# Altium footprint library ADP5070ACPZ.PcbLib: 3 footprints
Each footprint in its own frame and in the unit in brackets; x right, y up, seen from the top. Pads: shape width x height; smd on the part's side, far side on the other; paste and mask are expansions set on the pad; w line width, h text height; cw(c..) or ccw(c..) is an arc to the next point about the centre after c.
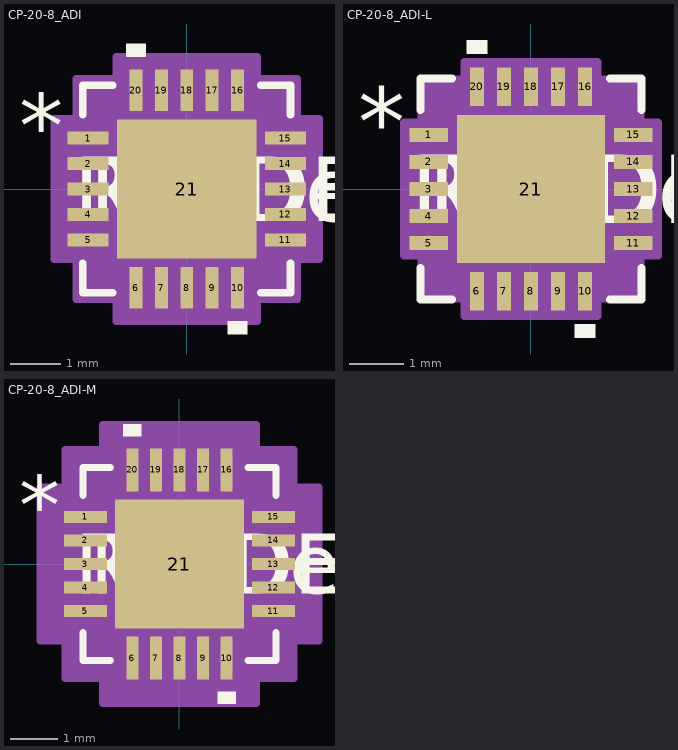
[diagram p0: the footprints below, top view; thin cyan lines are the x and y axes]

## CP-20-8_ADI [mil]
pads (21):
  rect 32x10 smd paste+0 mask+0: 1(-76.5,39.37) 2(-76.5,19.68) 3(-76.5,0) 4(-76.5,-19.68) 5(-76.5,-39.37) 11(76.5,-39.37) 12(76.5,-19.68) 13(76.5,0) 14(76.5,19.68) 15(76.5,39.37)
  rect 10x32 smd paste+0 mask+0: 6(-39.37,-76.5) 7(-19.68,-76.5) 8(0,-76.5) 9(19.68,-76.5) 10(39.37,-76.5) 16(39.37,76.5) 17(19.68,76.5) 18(0,76.5) 19(-19.68,76.5) 20(-39.37,76.5)
  rect 108x108 smd paste-54 mask+0: 21(0,0)
Top Overlay:
  region: 46.87,-102.5 31.87,-102.5 31.87,-112.5 46.87,-112.5
  region: -31.87,102.5 -46.87,102.5 -46.87,112.5 -31.87,112.5
  lines w6: -80.5,-57.47 -80.5,-80.5 -57.47,-80.5 ; -80.5,57.47 -80.5,80.5 -57.47,80.5 ; 57.47,-80.5 80.5,-80.5 80.5,-57.47 ; 57.47,80.5 80.5,80.5 80.5,57.47
  text "*" at -130,24.21 h50
  text "RefDes" at -75,-25 h50
  text "REFDES" at -87.5,-25 h50
Top Paste:
  region: -3.94,50.06 -50.06,50.06 -50.06,3.94 -3.94,3.94
  region: -3.94,-3.94 -50.06,-3.94 -50.06,-50.06 -3.94,-50.06
  region: 50.06,50.06 3.94,50.06 3.94,3.94 50.06,3.94
  region: 50.06,-3.94 3.94,-3.94 3.94,-50.06 50.06,-50.06
Mechanical 13:
  lines w1: -75.5,25.5 -25.5,75.5 ; -75.5,-75.5 75.5,-75.5 ; -75.5,-75.5 -75.5,75.5 ; -75.5,-75.5 -75.5,-75.5 ; -75.5,75.5 75.5,75.5 ; -75.5,75.5 -75.5,75.5 ; 75.5,-75.5 75.5,-75.5 ; 75.5,-75.5 75.5,75.5 ; 75.5,75.5 75.5,75.5 ; -80.5,-45.37 -80.5,-33.37 -75.5,-33.37 -75.5,-45.37 -80.5,-45.37 ; -80.5,-25.68 -80.5,-13.69 -75.5,-13.69 -75.5,-25.68 -80.5,-25.68 ; -80.5,-6 -80.5,6 -75.5,6 -75.5,-6 -80.5,-6 ; -80.5,13.69 -80.5,25.68 -75.5,25.68 -75.5,13.69 -80.5,13.69 ; -80.5,33.37 -80.5,45.37 -75.5,45.37 -75.5,33.37 -80.5,33.37 ; -45.37,-80.5 -45.37,-75.5 -33.37,-75.5 -33.37,-80.5 -45.37,-80.5 ; -45.37,75.5 -33.37,75.5 -33.37,80.5 -45.37,80.5 -45.37,75.5 ; -25.68,-80.5 -25.68,-75.5 -13.69,-75.5 -13.69,-80.5 -25.68,-80.5 ; -25.68,75.5 -13.69,75.5 -13.69,80.5 -25.68,80.5 -25.68,75.5 ; -6,-80.5 -6,-75.5 6,-75.5 6,-80.5 -6,-80.5 ; -6,75.5 6,75.5 6,80.5 -6,80.5 -6,75.5 ; 13.69,-80.5 13.69,-75.5 25.68,-75.5 25.68,-80.5 13.69,-80.5 ; 13.69,75.5 25.68,75.5 25.68,80.5 13.69,80.5 13.69,75.5 ; 33.37,-80.5 33.37,-75.5 45.37,-75.5 45.37,-80.5 33.37,-80.5 ; 33.37,75.5 45.37,75.5 45.37,80.5 33.37,80.5 33.37,75.5 ; 75.5,-45.37 75.5,-33.37 80.5,-33.37 80.5,-45.37 75.5,-45.37 ; 75.5,-25.68 75.5,-13.69 80.5,-13.69 80.5,-25.68 75.5,-25.68 ; 75.5,-6 75.5,6 80.5,6 80.5,-6 75.5,-6 ; 75.5,13.69 75.5,25.68 80.5,25.68 80.5,13.69 75.5,13.69 ; 75.5,33.37 75.5,45.37 80.5,45.37 80.5,33.37 75.5,33.37
  text "*" at -73,24.21 h50
  text "RefDes2" at -87.5,-25 h50
Mechanical 15:
  region: -54.37,-85.5 -85.5,-85.5 -85.5,-54.37 -102.5,-54.37 -102.5,54.37 -85.5,54.37 -85.5,85.5 -54.37,85.5 -54.37,102.5 54.37,102.5 54.37,85.5 85.5,85.5 85.5,54.37 102.5,54.37 102.5,-54.37 85.5,-54.37 85.5,-85.5 54.37,-85.5 54.37,-102.5 -54.37,-102.5
  lines w6: -102.5,-54.37 -85.5,-54.37 -85.5,-85.5 -54.37,-85.5 -54.37,-102.5 54.37,-102.5 54.37,-85.5 85.5,-85.5 85.5,-54.37 102.5,-54.37 102.5,54.37 85.5,54.37 85.5,85.5 54.37,85.5 54.37,102.5 -54.37,102.5 -54.37,85.5 -85.5,85.5 -85.5,54.37 -102.5,54.37 -102.5,-54.37
3D body "CP-20-8_ADI.step": height 32.09, standoff 0, extent -80.51,-80.51 80.51,80.51

## CP-20-8_ADI-L [mil]
pads (21):
  rect 28x10 smd paste+0 mask+0: 1(-74.5,39.37) 2(-74.5,19.68) 3(-74.5,0) 4(-74.5,-19.68) 5(-74.5,-39.37) 11(74.5,-39.37) 12(74.5,-19.68) 13(74.5,0) 14(74.5,19.68) 15(74.5,39.37)
  rect 10x28 smd paste+0 mask+0: 6(-39.37,-74.5) 7(-19.68,-74.5) 8(0,-74.5) 9(19.68,-74.5) 10(39.37,-74.5) 16(39.37,74.5) 17(19.68,74.5) 18(0,74.5) 19(-19.68,74.5) 20(-39.37,74.5)
  rect 108x108 smd paste-54 mask+0: 21(0,0)
Top Overlay:
  region: 46.87,-98.5 31.87,-98.5 31.87,-108.5 46.87,-108.5
  region: -31.87,98.5 -46.87,98.5 -46.87,108.5 -31.87,108.5
  lines w6: -80.5,-57.47 -80.5,-80.5 -57.47,-80.5 ; -80.5,57.47 -80.5,80.5 -57.47,80.5 ; 57.47,-80.5 80.5,-80.5 80.5,-57.47 ; 57.47,80.5 80.5,80.5 80.5,57.47
  text "*" at -126,24.21 h50
  text "RefDes" at -75,-25 h50
  text "REFDES" at -87.5,-25 h50
Top Paste:
  region: -3.94,50.06 -50.06,50.06 -50.06,3.94 -3.94,3.94
  region: -3.94,-3.94 -50.06,-3.94 -50.06,-50.06 -3.94,-50.06
  region: 50.06,50.06 3.94,50.06 3.94,3.94 50.06,3.94
  region: 50.06,-3.94 3.94,-3.94 3.94,-50.06 50.06,-50.06
Mechanical 13:
  lines w1: -75.5,25.5 -25.5,75.5 ; -75.5,-75.5 75.5,-75.5 ; -75.5,-75.5 -75.5,75.5 ; -75.5,-75.5 -75.5,-75.5 ; -75.5,75.5 75.5,75.5 ; -75.5,75.5 -75.5,75.5 ; 75.5,-75.5 75.5,-75.5 ; 75.5,-75.5 75.5,75.5 ; 75.5,75.5 75.5,75.5 ; -80.5,-45.37 -80.5,-33.37 -75.5,-33.37 -75.5,-45.37 -80.5,-45.37 ; -80.5,-25.68 -80.5,-13.69 -75.5,-13.69 -75.5,-25.68 -80.5,-25.68 ; -80.5,-6 -80.5,6 -75.5,6 -75.5,-6 -80.5,-6 ; -80.5,13.69 -80.5,25.68 -75.5,25.68 -75.5,13.69 -80.5,13.69 ; -80.5,33.37 -80.5,45.37 -75.5,45.37 -75.5,33.37 -80.5,33.37 ; -45.37,-80.5 -45.37,-75.5 -33.37,-75.5 -33.37,-80.5 -45.37,-80.5 ; -45.37,75.5 -33.37,75.5 -33.37,80.5 -45.37,80.5 -45.37,75.5 ; -25.68,-80.5 -25.68,-75.5 -13.69,-75.5 -13.69,-80.5 -25.68,-80.5 ; -25.68,75.5 -13.69,75.5 -13.69,80.5 -25.68,80.5 -25.68,75.5 ; -6,-80.5 -6,-75.5 6,-75.5 6,-80.5 -6,-80.5 ; -6,75.5 6,75.5 6,80.5 -6,80.5 -6,75.5 ; 13.69,-80.5 13.69,-75.5 25.68,-75.5 25.68,-80.5 13.69,-80.5 ; 13.69,75.5 25.68,75.5 25.68,80.5 13.69,80.5 13.69,75.5 ; 33.37,-80.5 33.37,-75.5 45.37,-75.5 45.37,-80.5 33.37,-80.5 ; 33.37,75.5 45.37,75.5 45.37,80.5 33.37,80.5 33.37,75.5 ; 75.5,-45.37 75.5,-33.37 80.5,-33.37 80.5,-45.37 75.5,-45.37 ; 75.5,-25.68 75.5,-13.69 80.5,-13.69 80.5,-25.68 75.5,-25.68 ; 75.5,-6 75.5,6 80.5,6 80.5,-6 75.5,-6 ; 75.5,13.69 75.5,25.68 80.5,25.68 80.5,13.69 75.5,13.69 ; 75.5,33.37 75.5,45.37 80.5,45.37 80.5,33.37 75.5,33.37
  text "*" at -73,24.21 h50
  text "RefDes2" at -87.5,-25 h50
Mechanical 15:
  region: -48.37,-79.5 -79.5,-79.5 -79.5,-48.37 -92.5,-48.37 -92.5,48.37 -79.5,48.37 -79.5,79.5 -48.37,79.5 -48.37,92.5 48.37,92.5 48.37,79.5 79.5,79.5 79.5,48.37 92.5,48.37 92.5,-48.37 79.5,-48.37 79.5,-79.5 48.37,-79.5 48.37,-92.5 -48.37,-92.5
  lines w6: -92.5,-48.37 -79.5,-48.37 -79.5,-79.5 -48.37,-79.5 -48.37,-92.5 48.37,-92.5 48.37,-79.5 79.5,-79.5 79.5,-48.37 92.5,-48.37 92.5,48.37 79.5,48.37 79.5,79.5 48.37,79.5 48.37,92.5 -48.37,92.5 -48.37,79.5 -79.5,79.5 -79.5,48.37 -92.5,48.37 -92.5,-48.37
3D body "CP-20-8_ADI.step": height 32.09, standoff 0, extent -80.51,-80.51 80.51,80.51

## CP-20-8_ADI-M [mil]
pads (21):
  rect 36x10 smd paste+0 mask+0: 1(-78.5,39.37) 2(-78.5,19.68) 3(-78.5,0) 4(-78.5,-19.68) 5(-78.5,-39.37) 11(78.5,-39.37) 12(78.5,-19.68) 13(78.5,0) 14(78.5,19.68) 15(78.5,39.37)
  rect 10x36 smd paste+0 mask+0: 6(-39.37,-78.5) 7(-19.68,-78.5) 8(0,-78.5) 9(19.68,-78.5) 10(39.37,-78.5) 16(39.37,78.5) 17(19.68,78.5) 18(0,78.5) 19(-19.68,78.5) 20(-39.37,78.5)
  rect 108x108 smd paste-54 mask+0: 21(0,0)
Top Overlay:
  region: 46.87,-106.5 31.87,-106.5 31.87,-116.5 46.87,-116.5
  region: -31.87,106.5 -46.87,106.5 -46.87,116.5 -31.87,116.5
  lines w6: -80.5,-57.47 -80.5,-80.5 -57.47,-80.5 ; -80.5,57.47 -80.5,80.5 -57.47,80.5 ; 57.47,-80.5 80.5,-80.5 80.5,-57.47 ; 57.47,80.5 80.5,80.5 80.5,57.47
  text "*" at -134,24.21 h50
  text "RefDes" at -75,-25 h50
  text "REFDES" at -87.5,-25 h50
Top Paste:
  region: -3.94,50.06 -50.06,50.06 -50.06,3.94 -3.94,3.94
  region: -3.94,-3.94 -50.06,-3.94 -50.06,-50.06 -3.94,-50.06
  region: 50.06,50.06 3.94,50.06 3.94,3.94 50.06,3.94
  region: 50.06,-3.94 3.94,-3.94 3.94,-50.06 50.06,-50.06
Mechanical 13:
  lines w1: -75.5,25.5 -25.5,75.5 ; -75.5,-75.5 75.5,-75.5 ; -75.5,-75.5 -75.5,75.5 ; -75.5,-75.5 -75.5,-75.5 ; -75.5,75.5 75.5,75.5 ; -75.5,75.5 -75.5,75.5 ; 75.5,-75.5 75.5,-75.5 ; 75.5,-75.5 75.5,75.5 ; 75.5,75.5 75.5,75.5 ; -80.5,-45.37 -80.5,-33.37 -75.5,-33.37 -75.5,-45.37 -80.5,-45.37 ; -80.5,-25.68 -80.5,-13.69 -75.5,-13.69 -75.5,-25.68 -80.5,-25.68 ; -80.5,-6 -80.5,6 -75.5,6 -75.5,-6 -80.5,-6 ; -80.5,13.69 -80.5,25.68 -75.5,25.68 -75.5,13.69 -80.5,13.69 ; -80.5,33.37 -80.5,45.37 -75.5,45.37 -75.5,33.37 -80.5,33.37 ; -45.37,-80.5 -45.37,-75.5 -33.37,-75.5 -33.37,-80.5 -45.37,-80.5 ; -45.37,75.5 -33.37,75.5 -33.37,80.5 -45.37,80.5 -45.37,75.5 ; -25.68,-80.5 -25.68,-75.5 -13.69,-75.5 -13.69,-80.5 -25.68,-80.5 ; -25.68,75.5 -13.69,75.5 -13.69,80.5 -25.68,80.5 -25.68,75.5 ; -6,-80.5 -6,-75.5 6,-75.5 6,-80.5 -6,-80.5 ; -6,75.5 6,75.5 6,80.5 -6,80.5 -6,75.5 ; 13.69,-80.5 13.69,-75.5 25.68,-75.5 25.68,-80.5 13.69,-80.5 ; 13.69,75.5 25.68,75.5 25.68,80.5 13.69,80.5 13.69,75.5 ; 33.37,-80.5 33.37,-75.5 45.37,-75.5 45.37,-80.5 33.37,-80.5 ; 33.37,75.5 45.37,75.5 45.37,80.5 33.37,80.5 33.37,75.5 ; 75.5,-45.37 75.5,-33.37 80.5,-33.37 80.5,-45.37 75.5,-45.37 ; 75.5,-25.68 75.5,-13.69 80.5,-13.69 80.5,-25.68 75.5,-25.68 ; 75.5,-6 75.5,6 80.5,6 80.5,-6 75.5,-6 ; 75.5,13.69 75.5,25.68 80.5,25.68 80.5,13.69 75.5,13.69 ; 75.5,33.37 75.5,45.37 80.5,45.37 80.5,33.37 75.5,33.37
  text "*" at -73,24.21 h50
  text "RefDes2" at -87.5,-25 h50
Mechanical 15:
  region: -64.37,-95.5 -95.5,-95.5 -95.5,-64.37 -116.5,-64.37 -116.5,64.37 -95.5,64.37 -95.5,95.5 -64.37,95.5 -64.37,116.5 64.37,116.5 64.37,95.5 95.5,95.5 95.5,64.37 116.5,64.37 116.5,-64.37 95.5,-64.37 95.5,-95.5 64.37,-95.5 64.37,-116.5 -64.37,-116.5
  lines w6: -116.5,-64.37 -95.5,-64.37 -95.5,-95.5 -64.37,-95.5 -64.37,-116.5 64.37,-116.5 64.37,-95.5 95.5,-95.5 95.5,-64.37 116.5,-64.37 116.5,64.37 95.5,64.37 95.5,95.5 64.37,95.5 64.37,116.5 -64.37,116.5 -64.37,95.5 -95.5,95.5 -95.5,64.37 -116.5,64.37 -116.5,-64.37
3D body "CP-20-8_ADI.step": height 32.09, standoff 0, extent -80.51,-80.51 80.51,80.51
